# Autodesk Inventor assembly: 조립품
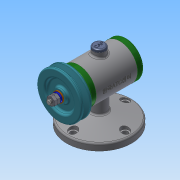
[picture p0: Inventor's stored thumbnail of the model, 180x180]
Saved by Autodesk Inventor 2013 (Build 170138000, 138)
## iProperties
Created: 2018-12
Part Number: 조립품
Document SubType Name: Assembly
Designer: Administrator
Author: Administrator
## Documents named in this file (14)
- C:\Users\Administrator\Desktop\481207V1035\조립품.iam
- C:\Users\Administrator\Desktop\481207V1035\본체.ipt
- C:\Users\Administrator\Desktop\481207V1035\베어링 15 x 32 x 9.ipt
- C:\Users\Administrator\Desktop\481207V1035\뒤커버.ipt
- C:\Users\Administrator\Desktop\481207V1035\볼트 M4 x 12.ipt
- C:\Users\Administrator\Desktop\481207V1035\축.ipt
- C:\Users\Administrator\Desktop\481207V1035\키 3 x 3 x 12.ipt
- C:\Users\Administrator\Desktop\481207V1035\앞커버.ipt
- C:\Users\Administrator\Desktop\481207V1035\V벨트풀리.ipt
- C:\Users\Administrator\Desktop\481207V1035\스프링와셔 8.ipt
- C:\Users\Administrator\Desktop\481207V1035\와셔 8x17.ipt
- C:\Users\Administrator\Desktop\481207V1035\너트 M8.ipt
- 너트 M8.ipt
- C:\Users\Administrator\Desktop\481207V1035\고무캡.ipt
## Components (2 placed, 2 different names)
1. V벨트풀리:1
2. 고무캡:1
